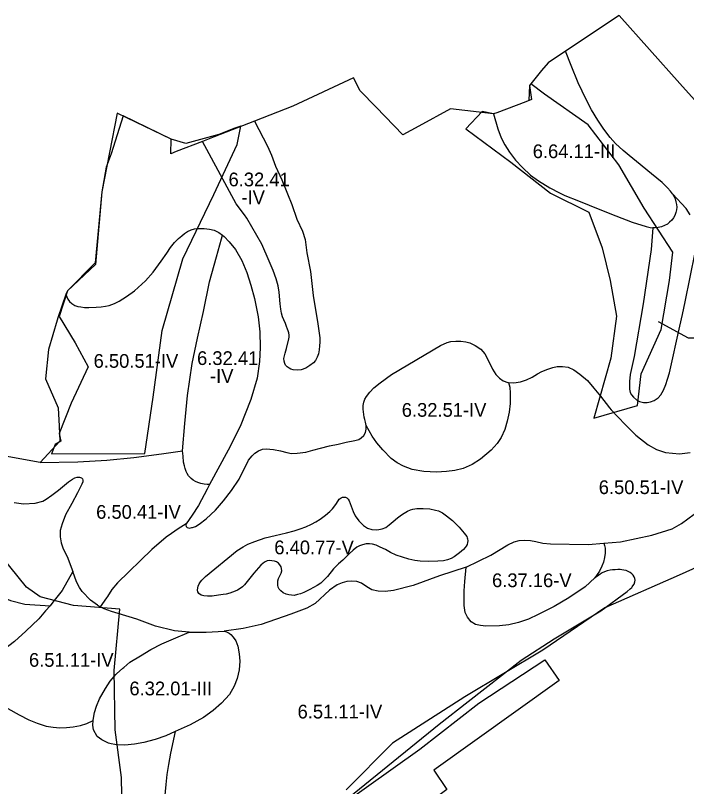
# Model space of a CAD drawing. Extents: x -555156 to -540209, y -1046851 to -1035695.
# Drawn here: x -542589 to -542099, y -1037432 to -1036870 of the extents above; entities that cross this region are included whole.
import ezdxf

# ---------------------------------------------------------------- set-up
doc = ezdxf.new("R2010")
doc.units = 0
for name, color, linetype in [('Vrstva 27', 7, 'Continuous'), ('Vrstva 28', 7, 'Continuous'), ('Vrstva 29', 7, 'Continuous')]:
    doc.layers.add(name, color=color, linetype=linetype)

msp = doc.modelspace()

# ---------------------------------------------------------------- linework, layer by layer
at = {"layer": 'Vrstva 27'}
msp.add_lwpolyline([(-542120.1, -1037093.16), (-542098.37, -1037105.09), (-542042.54, -1037105.09)], dxfattribs=at)
at = {"layer": 'Vrstva 28'}
for points in [[(-541903.43, -1036929.77), (-541905.13, -1036938.4), (-541936.81, -1036947.75), (-541968.13, -1036960.14), (-542007.23, -1036969.46), (-542041.47, -1036967.02), (-542067.69, -1036951.35), (-542068.09, -1036951.11), (-542075.71, -1036946.82), (-542081.37, -1036944.35), (-542083, -1036943.64), (-542104.38, -1036919.7), (-542148.57, -1036870.22), (-542187.73, -1036896.2)], [(-542187.73, -1036896.2), (-542200.49, -1036904.66), (-542205.18, -1036910.39), (-542214.08, -1036921.26), (-542212.47, -1036931.51), (-542216.58, -1036933.07), (-542237.71, -1036941.07), (-542240.22, -1036942.02)], [(-542109.82, -1037000.16), (-542111.21, -1036998.22), (-542113.29, -1036995.86), (-542117.36, -1036991.88), (-542125.09, -1036985.54), (-542135.94, -1036976.71), (-542141.28, -1036972.18), (-542145.82, -1036968.53), (-542151.24, -1036963.59), (-542155.13, -1036959.22), (-542159.76, -1036953.18), (-542164.29, -1036946.52), (-542168.83, -1036939.01), (-542172.79, -1036931.5), (-542178.46, -1036919.31), (-542183.7, -1036906.7), (-542187.73, -1036896.2)], [(-542240.22, -1036942.02), (-542271.64, -1036938.39), (-542294.61, -1036950.84), (-542306.42, -1036957.24), (-542325.81, -1036937.08), (-542337.3, -1036925.14), (-542342.26, -1036915.59), (-542386.58, -1036936.27), (-542414.3, -1036947.18)], [(-542452.27, -1036962.05), (-542471.5, -1036969.45), (-542475.46, -1036970.97), (-542475.26, -1036960.36), (-542507.39, -1036944.78), (-542514.44, -1036941.36), (-542525.74, -1036998.83), (-542530.63, -1037050.57), (-542550.84, -1037070.8), (-542551.82, -1037073.57)], [(-542240.22, -1036942.02), (-542237.13, -1036952.9), (-542234.58, -1036959.28), (-542232.03, -1036964.53), (-542228.63, -1036969.77), (-542224.24, -1036975.72), (-542219.14, -1036981.11), (-542213.19, -1036986.49), (-542207.38, -1036990.75), (-542199.16, -1036995.85), (-542192.1, -1036999.38), (-542188.12, -1037001.37), (-542178.34, -1037005.34), (-542162.76, -1037011.58), (-542151, -1037016.11), (-542139.1, -1037020.79), (-542128.91, -1037023.91), (-542126.04, -1037024.61), (-542124.19, -1037024.89)], [(-542414.3, -1036947.18), (-542443.74, -1036958.77), (-542452.27, -1036962.05)], [(-542414.3, -1036947.18), (-542404.91, -1036965.51), (-542401.99, -1036971.99), (-542399.06, -1036979.93), (-542394.47, -1036990.1), (-542390.43, -1037000.13), (-542387.09, -1037007.94), (-542383.47, -1037018.66), (-542379.54, -1037027.41), (-542377.59, -1037033.4), (-542376.34, -1037043.15), (-542373.55, -1037056.8), (-542371.74, -1037074.22), (-542368.26, -1037094.84), (-542367.26, -1037101.71), (-542366.8, -1037104.98), (-542366.85, -1037108.3), (-542367.12, -1037110.81), (-542367.39, -1037113.76), (-542367.89, -1037116.72), (-542368.76, -1037119.22), (-542369.87, -1037121.63), (-542371.46, -1037123.41), (-542374.1, -1037125.27), (-542376.96, -1037127.18), (-542380.46, -1037128.41)], [(-542380.46, -1037128.41), (-542383.15, -1037128.64), (-542386.15, -1037128.41), (-542387.83, -1037127.96), (-542389.19, -1037127.14), (-542390.56, -1037126.14), (-542391.74, -1037124.95), (-542392.42, -1037123.68), (-542392.88, -1037122.04), (-542392.92, -1037120.22), (-542392.56, -1037118.22), (-542391.97, -1037116.27), (-542391.1, -1037112.81), (-542389.33, -1037105.94), (-542389.16, -1037104.61), (-542389.19, -1037103.23), (-542389.4, -1037101.57), (-542389.79, -1037100.11), (-542390.33, -1037098.73), (-542391.03, -1037096.89), (-542391.92, -1037094.73), (-542393.14, -1037092.03), (-542394.07, -1037089.7), (-542394.79, -1037087.2), (-542395.29, -1037084.29), (-542395.66, -1037080.33), (-542396.43, -1037071.79), (-542397.25, -1037067.29), (-542398.7, -1037062.05), (-542400.7, -1037055.96), (-542403.75, -1037049.27), (-542409.1, -1037036.76), (-542419.92, -1037017.9), (-542421.79, -1037015.43), (-542427.88, -1037007.39), (-542452.27, -1036962.05)], [(-542109.82, -1037000.16), (-542108.85, -1037001.88), (-542107.91, -1037003.88), (-542107.22, -1037006.05), (-542106.85, -1037008), (-542106.71, -1037009.89), (-542106.8, -1037011.74), (-542107.26, -1037013.87), (-542108.1, -1037015.91), (-542109.02, -1037017.71), (-542110.32, -1037019.38), (-542111.94, -1037020.95), (-542113.46, -1037022.25), (-542115.5, -1037023.36), (-542117.86, -1037024.19), (-542120.12, -1037024.66), (-542122.48, -1037024.89), (-542123.75, -1037024.89), (-542124.19, -1037024.89)], [(-542096.85, -1037015.48), (-542099.83, -1037010.94), (-542109.82, -1037000.16)], [(-542551.82, -1037073.57), (-542550.49, -1037077.02), (-542549.35, -1037078.66), (-542547.63, -1037080.16), (-542545.35, -1037081.48), (-542543.31, -1037082.25), (-542540.94, -1037082.61), (-542538.25, -1037082.96), (-542535.16, -1037083.01), (-542529.8, -1037082.87), (-542526.3, -1037082.6), (-542523.11, -1037082.14), (-542520.25, -1037081.46), (-542516.57, -1037080.05), (-542513.11, -1037078.27), (-542507.7, -1037074.95), (-542501.94, -1037070.75), (-542493.83, -1037063.51), (-542488.34, -1037057.14), (-542482.53, -1037049.18), (-542478.41, -1037043.43), (-542475.59, -1037039.29), (-542472.68, -1037035.61), (-542469.86, -1037032.79), (-542467.36, -1037030.7), (-542465.36, -1037029.06), (-542463.27, -1037027.69), (-542460.54, -1037026.51), (-542458.13, -1037025.69), (-542455.49, -1037025.33), (-542451.18, -1037025.33), (-542447.13, -1037025.87), (-542443.83, -1037026.75), (-542443.72, -1037026.78), (-542440.51, -1037028.46), (-542437.81, -1037030.29)], [(-542124.19, -1037024.89), (-542125.38, -1037040.75), (-542131.04, -1037080.44), (-542137.67, -1037118.6), (-542140.51, -1037131.72), (-542141.07, -1037136.9), (-542141.07, -1037140.46), (-542141.07, -1037142.57), (-542140.51, -1037144.84), (-542139.62, -1037146.54), (-542138.08, -1037148.4), (-542135.97, -1037150.34), (-542133.87, -1037151.48), (-542130.79, -1037152.29), (-542129.61, -1037152.25), (-542128.2, -1037152.21), (-542125.78, -1037151.72), (-542123.19, -1037150.83), (-542120.27, -1037148.81), (-542118.25, -1037146.62), (-542116.31, -1037143.14), (-542114.61, -1037139.09), (-542113.31, -1037135.2), (-542112.01, -1037130.49), (-542104.29, -1037096.65), (-542102.34, -1037088.08), (-542100.5, -1037078.84), (-542093.31, -1037042.83)], [(-542447.1, -1037064.41), (-542442.23, -1037046.12), (-542438.58, -1037033.04), (-542437.81, -1037030.29)], [(-542437.81, -1037030.29), (-542436.53, -1037031.16), (-542432.87, -1037035.06), (-542428.34, -1037040.72), (-542423.64, -1037048.68), (-542420.06, -1037057.43), (-542417.12, -1037066.71), (-542414.49, -1037076.5), (-542411.79, -1037089.79), (-542410.59, -1037100.78), (-542410.31, -1037112.22), (-542410.86, -1037122.25), (-542412.54, -1037134.51), (-542416.99, -1037149.98), (-542424.79, -1037169.76), (-542433.6, -1037187.03), (-542447.1, -1037211.9)], [(-542466.81, -1037187.32), (-542465.14, -1037167.53), (-542463.19, -1037147.06), (-542459.77, -1037123.89), (-542455.88, -1037105.37), (-542451.49, -1037085.86), (-542447.1, -1037064.41)], [(-542551.82, -1037073.57), (-542557.85, -1037090.63), (-542558.29, -1037092.13), (-542564.61, -1037113.6), (-542566.78, -1037134.99), (-542557.49, -1037156.02), (-542556.85, -1037169.44), (-542556.34, -1037180.26), (-542570.54, -1037195.82)], [(-542332.93, -1037169.03), (-542333.43, -1037166.48), (-542333.88, -1037164.62), (-542334.41, -1037162.84), (-542334.82, -1037160.97), (-542335.05, -1037159.11), (-542335.18, -1037156.97), (-542335.18, -1037154.33), (-542334.82, -1037152.05), (-542333.91, -1037149.78), (-542332.82, -1037147.78), (-542330.44, -1037144.76), (-542327.5, -1037141.5), (-542322.72, -1037137.76), (-542314.61, -1037131.87), (-542278.88, -1037110.77), (-542274.09, -1037108.52), (-542271.22, -1037107.73), (-542267.64, -1037107.41), (-542263.98, -1037107.41), (-542260.4, -1037108.05), (-542257.46, -1037108.76), (-542253.48, -1037110.67), (-542249.5, -1037113.46), (-542246.56, -1037116.8), (-542243.77, -1037121.9), (-542240.95, -1037127.9), (-542238.56, -1037131.8), (-542235.94, -1037134.51), (-542233.23, -1037136.42), (-542229.65, -1037137.53), (-542229.19, -1037137.56)], [(-542570.54, -1037195.82), (-542596.19, -1037191.22), (-542614.09, -1037175.43), (-542651.98, -1037149.77), (-542647.45, -1037135.49), (-542658.9, -1037119.98)], [(-542229.19, -1037137.56), (-542225.35, -1037137.85), (-542220.58, -1037137.21), (-542216.2, -1037135.78), (-542212.07, -1037133.79), (-542208.03, -1037131.27), (-542204.93, -1037129.6), (-542200.55, -1037128.01), (-542196.97, -1037126.73), (-542193.71, -1037126.1), (-542189.81, -1037125.94), (-542185.75, -1037126.57), (-542181.77, -1037128.41), (-542177.32, -1037131.59), (-542171.75, -1037136.21)], [(-542229.19, -1037137.56), (-542228.42, -1037141.15), (-542228.1, -1037145.51), (-542228.1, -1037152.88), (-542228.81, -1037159.25), (-542230.37, -1037165.91), (-542232.07, -1037171.87), (-542234.62, -1037177.68), (-542237.59, -1037182.07), (-542241.99, -1037187.03), (-542249.78, -1037193.41), (-542255.73, -1037197.38), (-542262.38, -1037200.21), (-542268.47, -1037201.63), (-542274.57, -1037202.48)], [(-542171.75, -1037136.21), (-542167.03, -1037141.74), (-542162.18, -1037147.71), (-542155.71, -1037156), (-542154.54, -1037157.5), (-542144.36, -1037168.33), (-542138.26, -1037174.37), (-542136.57, -1037176.04), (-542127.52, -1037183.15), (-542121.53, -1037186.49), (-542114.85, -1037188.58), (-542104.68, -1037189.56), (-542096.89, -1037188.58)], [(-542464.18, -1037240.65), (-542464.5, -1037241.56), (-542464.27, -1037242.65), (-542463.45, -1037243.38), (-542461.77, -1037243.7), (-542460.18, -1037243.37), (-542459.63, -1037243.25), (-542457.31, -1037242.52), (-542454.72, -1037240.74), (-542449.63, -1037236.88), (-542442.81, -1037230.69), (-542437.09, -1037223.96), (-542431.2, -1037216.32), (-542425.71, -1037208.04), (-542423.07, -1037203.01), (-542421.08, -1037198.87), (-542418.69, -1037194.26), (-542416.23, -1037191.07), (-542414.16, -1037189.15), (-542411.62, -1037187.32), (-542408.67, -1037186.28), (-542405.97, -1037185.96), (-542400.48, -1037186.36), (-542395.47, -1037187.4), (-542390.93, -1037188.75), (-542387.43, -1037189.31), (-542383.21, -1037189.15), (-542377.09, -1037188.35), (-542371.99, -1037186.92), (-542366.35, -1037185.41), (-542359.74, -1037183.81), (-542353.39, -1037182.49), (-542347.5, -1037181.14), (-542341.29, -1037179.94), (-542338.39, -1037179.04), (-542336.61, -1037177.94), (-542334.7, -1037176.17), (-542333.57, -1037174.08), (-542333.02, -1037171.71), (-542332.93, -1037169.03)], [(-542274.57, -1037202.48), (-542281.83, -1037202.94), (-542291.03, -1037202.52), (-542299.39, -1037201.1), (-542305.76, -1037198.69), (-542310.44, -1037196.14), (-542314.69, -1037193.02), (-542320.92, -1037186.78), (-542325.17, -1037181.68), (-542328.71, -1037176.72), (-542332.93, -1037169.03)], [(-542704.76, -1037181.21), (-542691.64, -1037207.59), (-542691.59, -1037207.69), (-542687.89, -1037213.86), (-542682.67, -1037222.57), (-542673.25, -1037235.47), (-542662.59, -1037247.87), (-542649.7, -1037260.27), (-542638.3, -1037269.44), (-542623.92, -1037279.86), (-542612.27, -1037286.81), (-542611.77, -1037287.07), (-542601.86, -1037292.26), (-542601.09, -1037292.6), (-542598.32, -1037293.8), (-542592.19, -1037296.48), (-542581.78, -1037299.21), (-542563.36, -1037300.23)], [(-542570.54, -1037195.82), (-542543.11, -1037195.54), (-542522.08, -1037194.14), (-542502.31, -1037192.19), (-542482.26, -1037189.68), (-542466.81, -1037187.32)], [(-542447.1, -1037211.9), (-542448.97, -1037211.96), (-542451.15, -1037211.73), (-542453.56, -1037211.23), (-542455.61, -1037210.55), (-542457.43, -1037209.69), (-542459.2, -1037208.69), (-542460.7, -1037207.46), (-542462.43, -1037205.59), (-542463.52, -1037204.05), (-542464.34, -1037202.41), (-542465.07, -1037200.27), (-542465.55, -1037198.39), (-542466.11, -1037195.61), (-542466.43, -1037191.39), (-542466.81, -1037187.32)], [(-542589.69, -1037224.96), (-542582.73, -1037226.08), (-542574.23, -1037225.66), (-542568.72, -1037224), (-542566.33, -1037222.73), (-542562.04, -1037219.7), (-542557.38, -1037216), (-542549.92, -1037209.95), (-542547.19, -1037208), (-542545.42, -1037207.09), (-542543.65, -1037206.63), (-542542.01, -1037206.68), (-542540.51, -1037207.13), (-542539.74, -1037207.91), (-542539.51, -1037208.77), (-542539.6, -1037209.91), (-542540.19, -1037211.68), (-542543.35, -1037217.92), (-542547.52, -1037225.72), (-542552.26, -1037233.94), (-542554.62, -1037240.63), (-542556.02, -1037245.37), (-542556.02, -1037249.96), (-542555.32, -1037254.42), (-542553.93, -1037258.88), (-542551, -1037264.45), (-542546.77, -1037275.32)], [(-542447.1, -1037211.9), (-542448.95, -1037215.31), (-542455.15, -1037227.28), (-542459.74, -1037234.38), (-542464.18, -1037240.65)], [(-542377, -1037242.78), (-542372.95, -1037240.91), (-542369.71, -1037239.05), (-542366.54, -1037237.12), (-542362.74, -1037234.28), (-542359.42, -1037231.69), (-542357.51, -1037229.56), (-542355.15, -1037226.42), (-542353.35, -1037223.73), (-542352.69, -1037222.69), (-542352.06, -1037222.03), (-542351.29, -1037221.56), (-542350.37, -1037221.29), (-542349.34, -1037221.16), (-542348.17, -1037221.29), (-542347.22, -1037221.69), (-542346.11, -1037222.72), (-542345.4, -1037223.91), (-542344.66, -1037225.68), (-542344.08, -1037227.64), (-542342.51, -1037231.51), (-542341.05, -1037234.75), (-542338.46, -1037238.31), (-542334.98, -1037241.8), (-542331.99, -1037243.66), (-542328.83, -1037244.63)], [(-542328.83, -1037244.63), (-542325.76, -1037244.87), (-542323.85, -1037244.76), (-542321.26, -1037244.29), (-542318.81, -1037243.23), (-542316.17, -1037241.38), (-542313.26, -1037238.93), (-542310.25, -1037236.29), (-542307.34, -1037234.02), (-542305.25, -1037232.72), (-542302.9, -1037231.43), (-542300.72, -1037230.5), (-542299.01, -1037229.95), (-542296.1, -1037229.49), (-542291.56, -1037229.44), (-542286.71, -1037229.76), (-542282.5, -1037230.55), (-542280.29, -1037231.13), (-542277.37, -1037232.57), (-542274.37, -1037234.69), (-542270.21, -1037238.21), (-542265.16, -1037243.02), (-542261.6, -1037247.28), (-542260.57, -1037248.57), (-542259.67, -1037249.82), (-542259.3, -1037250.69), (-542259.06, -1037251.64), (-542258.93, -1037252.94), (-542259.06, -1037254.28), (-542259.38, -1037255.58), (-542260.04, -1037256.88), (-542260.86, -1037257.91), (-542262.15, -1037259.2), (-542265.11, -1037261.66), (-542266.93, -1037263.25), (-542268.78, -1037264.68), (-542271.04, -1037265.89), (-542273.68, -1037266.9), (-542276.55, -1037267.64), (-542280.8, -1037267.88), (-542287.56, -1037268.06), (-542293.71, -1037267.83), (-542297.59, -1037267.37), (-542301.85, -1037266.3), (-542306.44, -1037264.97), (-542311.07, -1037263.35), (-542315.32, -1037261.41), (-542319.02, -1037259.37), (-542322.72, -1037257.52), (-542325.77, -1037256.23), (-542328.36, -1037255.35), (-542330.63, -1037255.16), (-542332.99, -1037255.21), (-542335.63, -1037255.81), (-542337.85, -1037256.55), (-542339.79, -1037257.61), (-542342.52, -1037259.79), (-542345.34, -1037262.52), (-542350.09, -1037266.99), (-542353.16, -1037269.74), (-542356.89, -1037273.47), (-542361.18, -1037279.06), (-542363.3, -1037281.16), (-542366.08, -1037283.75), (-542368.67, -1037285.46), (-542371.4, -1037287.08), (-542374.13, -1037288.38), (-542378.38, -1037290.51), (-542380.83, -1037291.5), (-542383.14, -1037292.19), (-542385.41, -1037292.7), (-542387.4, -1037292.57), (-542389.34, -1037292.33), (-542391.42, -1037291.78), (-542393.46, -1037290.9), (-542395.22, -1037289.42), (-542396.33, -1037288.12), (-542397.11, -1037286.73), (-542397.39, -1037285.39), (-542397.48, -1037283.77), (-542397.3, -1037282.15), (-542396.83, -1037280.35), (-542395.91, -1037278.59), (-542394.94, -1037276.51), (-542394.57, -1037274.75), (-542394.71, -1037273.17), (-542395.03, -1037272.02), (-542395.86, -1037270.4), (-542396.83, -1037269.29), (-542398.27, -1037268.36), (-542399.93, -1037267.76), (-542401.69, -1037267.48), (-542403.59, -1037267.39), (-542405.25, -1037267.62), (-542406.73, -1037268.18), (-542408.21, -1037269.15), (-542409.88, -1037270.63), (-542414.92, -1037276.55), (-542421.72, -1037285.04)], [(-542159.87, -1037254.68), (-542147.6, -1037253.6), (-542124.77, -1037248.87), (-542110.01, -1037244.13), (-542103.21, -1037240.44), (-542093.98, -1037233.67)], [(-542464.18, -1037240.65), (-542470.11, -1037244.24), (-542474.89, -1037247.56), (-542478.85, -1037250.31), (-542489.23, -1037259.31), (-542514.39, -1037283.62), (-542518.43, -1037288.42), (-542521.59, -1037293.44), (-542522.38, -1037294.6), (-542526.82, -1037301.12)], [(-542421.72, -1037285.04), (-542423.27, -1037286.42), (-542425.53, -1037288.13), (-542426.92, -1037288.97), (-542428.59, -1037289.71), (-542430.44, -1037290.36), (-542432.38, -1037291.05), (-542435.02, -1037291.74), (-542437.24, -1037292.16), (-542440.66, -1037292.58), (-542445.28, -1037293.18), (-542448.66, -1037293.18), (-542451.25, -1037293.09), (-542453.33, -1037292.48), (-542455.04, -1037291.37), (-542455.74, -1037290.17), (-542455.92, -1037288.83), (-542455.83, -1037287.3), (-542455.46, -1037286.05), (-542454.72, -1037284.34), (-542453.8, -1037282.81), (-542452.78, -1037281.52), (-542451.62, -1037280.36), (-542450.06, -1037279.03), (-542427.12, -1037260.04), (-542422.79, -1037257.29), (-542419.22, -1037255.43), (-542414.21, -1037253.56), (-542406.76, -1037250.73), (-542399.39, -1037249.03), (-542391.14, -1037247.08), (-542385.41, -1037245.61), (-542381.21, -1037244.15), (-542377, -1037242.78)], [(-542260.23, -1037272.16), (-542242.17, -1037263.41), (-542229.68, -1037255.84), (-542225.14, -1037253.77), (-542221.56, -1037252.82), (-542217.58, -1037252.58), (-542213.37, -1037252.66), (-542209.31, -1037253.38), (-542204.22, -1037254.57), (-542198.7, -1037255.27)], [(-542198.7, -1037255.27), (-542171.27, -1037255.69), (-542159.87, -1037254.68)], [(-542159.87, -1037254.68), (-542159.29, -1037256.41), (-542158.9, -1037258.4), (-542158.9, -1037261.9), (-542159.29, -1037265.01), (-542160.01, -1037268.43), (-542161.2, -1037271.54), (-542163, -1037274.96), (-542166.34, -1037279.97)], [(-542260.23, -1037272.16), (-542279.64, -1037278.49), (-542298.86, -1037285.59), (-542313.06, -1037289.07), (-542319.17, -1037289.89), (-542324.26, -1037289.73), (-542328.96, -1037288.62), (-542332.46, -1037286.39), (-542336.36, -1037283.84), (-542339.86, -1037282.57), (-542343.52, -1037282.25), (-542347.18, -1037282.65), (-542350.52, -1037283.52), (-542354.1, -1037285.03), (-542359.67, -1037288.86), (-542370.09, -1037298.73), (-542376.21, -1037302.12), (-542388.04, -1037306.44), (-542409.62, -1037313.97), (-542422.57, -1037316.75), (-542436.5, -1037318.84)], [(-542375.3, -1037464.1), (-542279.87, -1037386.5), (-542258.75, -1037370.05), (-542220.12, -1037339.95), (-542195.99, -1037324.35), (-542161.88, -1037303.87), (-542142.71, -1037289.78), (-542140.49, -1037287.92), (-542139.49, -1037286.97), (-542139.12, -1037286.52), (-542138.58, -1037285.87), (-542137.76, -1037284.46), (-542137.22, -1037282.87), (-542137.04, -1037281.6), (-542137.17, -1037280.37), (-542137.58, -1037279.19), (-542138.31, -1037277.91), (-542139.31, -1037276.96), (-542140.63, -1037276.05), (-542141.99, -1037275.32), (-542143.58, -1037274.64), (-542145.22, -1037274.23), (-542146.63, -1037274.05), (-542147.95, -1037273.96), (-542149.63, -1037273.96), (-542151.49, -1037274.05), (-542153.4, -1037274.18), (-542155.22, -1037274.41), (-542157.36, -1037274.82), (-542159.27, -1037275.5), (-542160.95, -1037276.32), (-542162.59, -1037277.37), (-542164.5, -1037278.82), (-542166.34, -1037279.97)], [(-542261.58, -1037289.44), (-542261.03, -1037282.62), (-542260.23, -1037272.16)], [(-542546.77, -1037275.32), (-542554.71, -1037289.14), (-542561.37, -1037297.67), (-542563.36, -1037300.23)], [(-542526.82, -1037301.12), (-542528.63, -1037300.16), (-542528.89, -1037299.96), (-542533.96, -1037296.1), (-542540.09, -1037289.81), (-542540.6, -1037289.07), (-542542, -1037287.02), (-542544.07, -1037282.88), (-542546.77, -1037275.32)], [(-542166.34, -1037279.97), (-542173.31, -1037286.38), (-542185.28, -1037294.46), (-542196, -1037300.87), (-542207.7, -1037306.72), (-542214.8, -1037310.06), (-542222.04, -1037312.57), (-542229.14, -1037314.1), (-542235.82, -1037314.94), (-542245.85, -1037315.08), (-542249.75, -1037314.66), (-542253.23, -1037313.82), (-542256.43, -1037311.87), (-542259.22, -1037308.67), (-542260.75, -1037305.19), (-542261.58, -1037300.03), (-542261.72, -1037295.29), (-542261.58, -1037289.44)], [(-542563.36, -1037300.23), (-542566.69, -1037304.01), (-542571.71, -1037309.72), (-542581.06, -1037318.8), (-542589.42, -1037326.31), (-542596.64, -1037331.83), (-542603.16, -1037336.23), (-542610.24, -1037339.49), (-542615.34, -1037341.19), (-542622.71, -1037342.18)], [(-542462.12, -1037319.54), (-542472.84, -1037318.56), (-542486.62, -1037315.22), (-542500.13, -1037310.13), (-542513.91, -1037305.81), (-542518.61, -1037304.46), (-542524.1, -1037302.55), (-542526.82, -1037301.12)], [(-542436.5, -1037318.84), (-542435.53, -1037318.99), (-542434.42, -1037319.41), (-542432.94, -1037320.29), (-542431.64, -1037321.3), (-542429.85, -1037323.25), (-542428.05, -1037325.9), (-542426.5, -1037329.72), (-542425.65, -1037335.39), (-542425.22, -1037340.64), (-542425.65, -1037347.01), (-542427.06, -1037353.25), (-542429.33, -1037358.92), (-542432.59, -1037364.87), (-542438.39, -1037371.25), (-542444.49, -1037376.63), (-542451.71, -1037381.59), (-542461.2, -1037386.98), (-542472.18, -1037391.98)], [(-542462.12, -1037319.54), (-542449.72, -1037319.54), (-542436.5, -1037318.84)], [(-542531.96, -1037383.95), (-542531.81, -1037382.2), (-542530.96, -1037378.09), (-542529.55, -1037373.41), (-542527.49, -1037368.14), (-542523.1, -1037360.63), (-542519.7, -1037355.1), (-542515.59, -1037350.28), (-542515.05, -1037349.82), (-542510.35, -1037345.75), (-542509.75, -1037345.25), (-542505.25, -1037341.49), (-542497.6, -1037336.68), (-542490.1, -1037332.14), (-542482.02, -1037328.03), (-542473.52, -1037324.35), (-542462.12, -1037319.54)], [(-542622.71, -1037342.18), (-542610.77, -1037360.12), (-542606.38, -1037365.54), (-542601.85, -1037369.37), (-542594.2, -1037375.04), (-542585.98, -1037379.86), (-542578.9, -1037383.4), (-542572.95, -1037385.81), (-542566.15, -1037387.94), (-542561.11, -1037388.75), (-542556.25, -1037389.23), (-542551.4, -1037389.07)], [(-542551.4, -1037389.07), (-542546.54, -1037388.5), (-542541.36, -1037387.53), (-542536.75, -1037386.07), (-542531.96, -1037383.95)], [(-542501.92, -1037401.19), (-542509.01, -1037401.75), (-542514.78, -1037401.53), (-542516.23, -1037401.47), (-542518.9, -1037400.83), (-542520.91, -1037400.34), (-542525.72, -1037397.93), (-542528.98, -1037395.52), (-542531.81, -1037390.56), (-542532.24, -1037387.16), (-542531.96, -1037383.95)], [(-542472.18, -1037391.98), (-542478.98, -1037394.95), (-542486.77, -1037397.79), (-542495.13, -1037399.91), (-542501.92, -1037401.19)], [(-542472.18, -1037391.98), (-542475.75, -1037407.64), (-542477.16, -1037415.86), (-542478.3, -1037423.09), (-542479.15, -1037430.46), (-542480.14, -1037440.8)]]:
    msp.add_lwpolyline(points, dxfattribs=at)
at = {"layer": 'Vrstva 29'}
for points in [[(-542213.127323, -1036920.096317), (-542214.08, -1036921.26), (-542214.45, -1036932.26), (-542216.58, -1036933.07), (-542237.71, -1036941.07), (-542240.22, -1036942.02), (-542248.435295, -1036940.107238), (-542260.315002, -1036952.758911), (-542227.632019, -1036977.109009), (-542198.583984, -1036999.747009), (-542170.789001, -1037013.544006), (-542161.078003, -1037039.500977), (-542155.195984, -1037063.210999), (-542150.622986, -1037089.322021), (-542154.786987, -1037120.015991), (-542167.132019, -1037163.539001), (-542135.315979, -1037154.294983), (-542132.585999, -1037131.356018), (-542117.997009, -1037099.093018), (-542111.942017, -1037063.255981), (-542109.481995, -1037042.585999), (-542130.515991, -1037010.677002), (-542148.77301, -1036979.098999), (-542171.14502, -1036949.843018), (-542203.059021, -1036927.630005), (-542213.127323, -1036920.096317)], [(-542424.444717, -1036950.791852), (-542428.69, -1036952.42), (-542440.36, -1036956.9), (-542464.36, -1036963.57), (-542475.26, -1036960.36), (-542510.104728, -1036943.462353), (-542518.971985, -1036971), (-542522.476593, -1036980.861604), (-542525.74, -1036998.83), (-542530.32, -1037051.58), (-542550.84, -1037070.8), (-542556.839862, -1037089.44881), (-542545.088013, -1037108.752991), (-542535.648987, -1037126.23999), (-542548.005005, -1037152.632996), (-542556.683483, -1037174.909468), (-542555.63, -1037180.44), (-542559.767372, -1037182.82539), (-542562.377014, -1037189.523987), (-542494.279907, -1037189.463013), (-542488.35199, -1037148.242004), (-542481.807007, -1037099.680908), (-542466.64502, -1037047.546021), (-542444.169006, -1037000.629028), (-542427.049988, -1036964.320984), (-542424.444717, -1036950.791852)], [(-542605.067993, -1037457.986023), (-542584.685913, -1037476.010986), (-542567.09198, -1037502.396912), (-542513.768982, -1037488.814026), (-542510.546997, -1037463.888), (-542511.348999, -1037425.443909), (-542515.911987, -1037390.642029), (-542516.64801, -1037347.348022), (-542512.632019, -1037302.83197), (-542546.349976, -1037300.088989), (-542570.695007, -1037293.862), (-542580.500977, -1037286.677979), (-542629.40802, -1037226.625977)], [(-542014.463, -1037435.867993), (-541935.387997, -1037405.927008), (-541957.756001, -1037372.324994), (-541984.616007, -1037320.547005), (-541994.651992, -1037293.018004), (-541995.386006, -1037234.639999), (-542055.756005, -1037255.819003), (-542104.990002, -1037278.069992), (-542159.007996, -1037301.796009), (-542204.153992, -1037332.715005), (-542261.167999, -1037366.566007), (-542313.831995, -1037400.424008), (-542347.578009, -1037434.492004)], [(-542444.48, -1037560.59), (-542458.41, -1037523.27), (-542456.95, -1037521.33), (-542443.05, -1037512.44), (-542371.62, -1037460.23), (-542293.97, -1037404.67), (-542250.85, -1037371.22), (-542202.69, -1037339.73), (-542192.28, -1037354.72), (-542283.67, -1037420.07), (-542274.19, -1037434.15), (-542433.32, -1037552.31), (-542444.48, -1037560.59)]]:
    msp.add_lwpolyline(points, dxfattribs=at)

# ---------------------------------------------------------------- texts
at = {"layer": 'Vrstva 27'}
for s, p in [('6.64.11-III', (-542211.616548, -1036974.18)), ('6.32.41', (-542433.353394, -1036994.72)), ('-IV', (-542423.923462, -1037007.72)), ('6.32.41', (-542456.283394, -1037124.88)), ('6.50.51-IV', (-542531.687241, -1037126.92)), ('-IV', (-542446.853462, -1037137.88)), ('6.32.51-IV', (-542307.087241, -1037162.61)), ('6.50.51-IV', (-542163.497241, -1037218.92)), ('6.50.41-IV', (-542529.847241, -1037236.92)), ('6.40.77-V', (-542399.992993, -1037262.76)), ('6.37.16-V', (-542241.277974, -1037286.72)), ('6.51.11-IV', (-542578.797241, -1037344.74)), ('6.32.01-III', (-542505.586548, -1037365.53)), ('6.51.11-IV', (-542383.017241, -1037382.4))]:
    msp.add_text(s, height=10, dxfattribs=at).set_placement(p)

doc.saveas('drawing.dxf')
